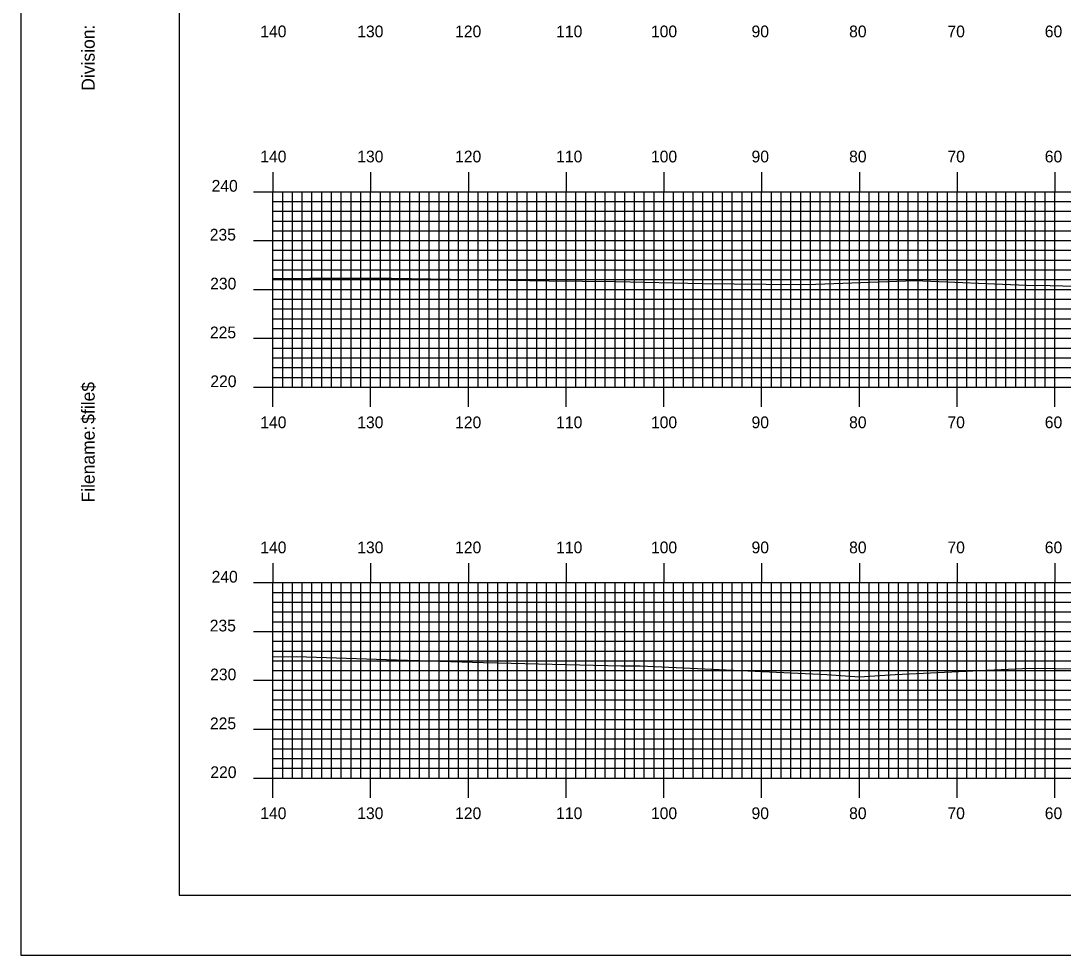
# Model space of a CAD drawing. Extents: x 1803503 to 1803847, y 442591 to 442811.
# Drawn here: x 1803503.4 to 1803610, y 442590.5 to 442686.2 of the extents above; entities that cross this region are included whole.
import ezdxf

# ---------------------------------------------------------------- set-up
doc = ezdxf.new("R2010")
doc.units = 0
for name, color, linetype in [('BORDER', 7, 'Continuous'), ('H_V ANNOTATION', 7, 'Continuous'), ('MAJOR', 7, 'Continuous'), ('MINOR', 7, 'Continuous'), ('PLOT BOUNDARY', 7, 'Continuous'), ('S_Roadway_Centerline', 7, 'Continuous')]:
    doc.layers.add(name, color=color, linetype=linetype)

msp = doc.modelspace()

# ---------------------------------------------------------------- linework, layer by layer
at = {"layer": 'BORDER'}
msp.add_lwpolyline([(1803519.54, 442596.67), (1803839.54, 442596.67), (1803839.54, 442806.67), (1803519.54, 442806.67)], close=True, dxfattribs=at)
at = {"layer": 'MAJOR'}
for p, q in [((1803529.14, 442670.67), (1803529.14, 442668.67)), ((1803539.14, 442670.67), (1803539.14, 442668.67)), ((1803549.14, 442670.67), (1803549.14, 442668.67)), ((1803559.14, 442670.67), (1803559.14, 442668.67)), ((1803569.14, 442670.67), (1803569.14, 442668.67)), ((1803579.14, 442670.67), (1803579.14, 442668.67)), ((1803589.14, 442670.67), (1803589.14, 442668.67)), ((1803599.14, 442670.67), (1803599.14, 442668.67)), ((1803609.14, 442670.67), (1803609.14, 442668.67)), ((1803527.14, 442668.67), (1803529.14, 442668.67)), ((1803529.14, 442668.67), (1803809.14, 442668.67)), ((1803529.14, 442648.67), (1803529.14, 442668.67)), ((1803529.14, 442648.67), (1803529.14, 442668.67)), ((1803529.14, 442668.67), (1803809.14, 442668.67)), ((1803539.14, 442648.67), (1803539.14, 442668.67)), ((1803549.14, 442648.67), (1803549.14, 442668.67)), ((1803559.14, 442648.67), (1803559.14, 442668.67)), ((1803569.14, 442648.67), (1803569.14, 442668.67)), ((1803579.14, 442648.67), (1803579.14, 442668.67)), ((1803589.14, 442648.67), (1803589.14, 442668.67)), ((1803599.14, 442648.67), (1803599.14, 442668.67)), ((1803609.14, 442648.67), (1803609.14, 442668.67)), ((1803527.14, 442663.67), (1803529.14, 442663.67)), ((1803529.14, 442663.67), (1803809.14, 442663.67)), ((1803527.14, 442658.67), (1803529.14, 442658.67)), ((1803529.14, 442658.67), (1803809.14, 442658.67)), ((1803527.14, 442653.67), (1803529.14, 442653.67)), ((1803529.14, 442653.67), (1803809.14, 442653.67)), ((1803527.14, 442648.67), (1803529.14, 442648.67)), ((1803529.14, 442648.67), (1803809.14, 442648.67)), ((1803529.14, 442648.67), (1803809.14, 442648.67)), ((1803529.14, 442646.66), (1803529.14, 442648.67)), ((1803539.14, 442646.66), (1803539.14, 442648.67)), ((1803549.14, 442646.66), (1803549.14, 442648.67)), ((1803559.14, 442646.66), (1803559.14, 442648.67)), ((1803569.14, 442646.66), (1803569.14, 442648.67)), ((1803579.14, 442646.66), (1803579.14, 442648.67)), ((1803589.14, 442646.66), (1803589.14, 442648.67)), ((1803599.14, 442646.66), (1803599.14, 442648.67)), ((1803609.14, 442646.66), (1803609.14, 442648.67)), ((1803529.14, 442630.67), (1803529.14, 442628.67)), ((1803539.14, 442630.67), (1803539.14, 442628.67)), ((1803549.14, 442630.67), (1803549.14, 442628.67)), ((1803559.14, 442630.67), (1803559.14, 442628.67)), ((1803569.14, 442630.67), (1803569.14, 442628.67)), ((1803579.14, 442630.67), (1803579.14, 442628.67)), ((1803589.14, 442630.67), (1803589.14, 442628.67)), ((1803599.14, 442630.67), (1803599.14, 442628.67)), ((1803609.14, 442630.67), (1803609.14, 442628.67)), ((1803527.14, 442628.67), (1803529.14, 442628.67)), ((1803529.14, 442628.67), (1803809.14, 442628.67)), ((1803529.14, 442608.67), (1803529.14, 442628.67)), ((1803529.14, 442608.67), (1803529.14, 442628.67)), ((1803529.14, 442628.67), (1803809.14, 442628.67)), ((1803539.14, 442608.67), (1803539.14, 442628.67)), ((1803549.14, 442608.67), (1803549.14, 442628.67)), ((1803559.14, 442608.67), (1803559.14, 442628.67)), ((1803569.14, 442608.67), (1803569.14, 442628.67)), ((1803579.14, 442608.67), (1803579.14, 442628.67)), ((1803589.14, 442608.67), (1803589.14, 442628.67)), ((1803599.14, 442608.67), (1803599.14, 442628.67)), ((1803609.14, 442608.67), (1803609.14, 442628.67)), ((1803527.14, 442623.67), (1803529.14, 442623.67)), ((1803529.14, 442623.67), (1803809.14, 442623.67)), ((1803527.14, 442618.67), (1803529.14, 442618.67)), ((1803529.14, 442618.67), (1803809.14, 442618.67)), ((1803527.14, 442613.67), (1803529.14, 442613.67)), ((1803529.14, 442613.67), (1803809.14, 442613.67)), ((1803527.14, 442608.67), (1803529.14, 442608.67)), ((1803529.14, 442608.67), (1803809.14, 442608.67)), ((1803529.14, 442608.67), (1803809.14, 442608.67)), ((1803529.14, 442606.66), (1803529.14, 442608.67)), ((1803539.14, 442606.66), (1803539.14, 442608.67)), ((1803549.14, 442606.66), (1803549.14, 442608.67)), ((1803559.14, 442606.66), (1803559.14, 442608.67)), ((1803569.14, 442606.66), (1803569.14, 442608.67)), ((1803579.14, 442606.66), (1803579.14, 442608.67)), ((1803589.14, 442606.66), (1803589.14, 442608.67)), ((1803599.14, 442606.66), (1803599.14, 442608.67)), ((1803609.14, 442606.66), (1803609.14, 442608.67))]:
    msp.add_line(p, q, dxfattribs=at)
at = {"layer": 'MINOR'}
for p, q in [((1803530.14, 442648.67), (1803530.14, 442668.67)), ((1803531.14, 442648.67), (1803531.14, 442668.67)), ((1803532.14, 442648.67), (1803532.14, 442668.67)), ((1803533.14, 442648.67), (1803533.14, 442668.67)), ((1803534.14, 442648.67), (1803534.14, 442668.67)), ((1803535.14, 442648.67), (1803535.14, 442668.67)), ((1803536.14, 442648.67), (1803536.14, 442668.67)), ((1803537.14, 442648.67), (1803537.14, 442668.67)), ((1803538.14, 442648.67), (1803538.14, 442668.67)), ((1803540.14, 442648.67), (1803540.14, 442668.67)), ((1803541.14, 442648.67), (1803541.14, 442668.67)), ((1803542.14, 442648.67), (1803542.14, 442668.67)), ((1803543.14, 442648.67), (1803543.14, 442668.67)), ((1803544.14, 442648.67), (1803544.14, 442668.67)), ((1803545.14, 442648.67), (1803545.14, 442668.67)), ((1803546.14, 442648.67), (1803546.14, 442668.67)), ((1803547.14, 442648.67), (1803547.14, 442668.67)), ((1803548.14, 442648.67), (1803548.14, 442668.67)), ((1803550.14, 442648.67), (1803550.14, 442668.67)), ((1803551.14, 442648.67), (1803551.14, 442668.67)), ((1803552.14, 442648.67), (1803552.14, 442668.67)), ((1803553.14, 442648.67), (1803553.14, 442668.67)), ((1803554.14, 442648.67), (1803554.14, 442668.67)), ((1803555.14, 442648.67), (1803555.14, 442668.67)), ((1803556.14, 442648.67), (1803556.14, 442668.67)), ((1803557.14, 442648.67), (1803557.14, 442668.67)), ((1803558.14, 442648.67), (1803558.14, 442668.67)), ((1803560.14, 442648.67), (1803560.14, 442668.67)), ((1803561.14, 442648.67), (1803561.14, 442668.67)), ((1803562.14, 442648.67), (1803562.14, 442668.67)), ((1803563.14, 442648.67), (1803563.14, 442668.67)), ((1803564.14, 442648.67), (1803564.14, 442668.67)), ((1803565.14, 442648.67), (1803565.14, 442668.67)), ((1803566.14, 442648.67), (1803566.14, 442668.67)), ((1803567.14, 442648.67), (1803567.14, 442668.67)), ((1803568.14, 442648.67), (1803568.14, 442668.67)), ((1803570.14, 442648.67), (1803570.14, 442668.67)), ((1803571.14, 442648.67), (1803571.14, 442668.67)), ((1803572.14, 442648.67), (1803572.14, 442668.67)), ((1803573.14, 442648.67), (1803573.14, 442668.67)), ((1803574.14, 442648.67), (1803574.14, 442668.67)), ((1803575.14, 442648.67), (1803575.14, 442668.67)), ((1803576.14, 442648.67), (1803576.14, 442668.67)), ((1803577.14, 442648.67), (1803577.14, 442668.67)), ((1803578.14, 442648.67), (1803578.14, 442668.67)), ((1803580.14, 442648.67), (1803580.14, 442668.67)), ((1803581.14, 442648.67), (1803581.14, 442668.67)), ((1803582.14, 442648.67), (1803582.14, 442668.67)), ((1803583.14, 442648.67), (1803583.14, 442668.67)), ((1803584.14, 442648.67), (1803584.14, 442668.67)), ((1803585.14, 442648.67), (1803585.14, 442668.67)), ((1803586.14, 442648.67), (1803586.14, 442668.67)), ((1803587.14, 442648.67), (1803587.14, 442668.67)), ((1803588.14, 442648.67), (1803588.14, 442668.67)), ((1803590.14, 442648.67), (1803590.14, 442668.67)), ((1803591.14, 442648.67), (1803591.14, 442668.67)), ((1803592.14, 442648.67), (1803592.14, 442668.67)), ((1803593.14, 442648.67), (1803593.14, 442668.67)), ((1803594.14, 442648.67), (1803594.14, 442668.67)), ((1803595.14, 442648.67), (1803595.14, 442668.67)), ((1803596.14, 442648.67), (1803596.14, 442668.67)), ((1803597.14, 442648.67), (1803597.14, 442668.67)), ((1803598.14, 442648.67), (1803598.14, 442668.67)), ((1803600.14, 442648.67), (1803600.14, 442668.67)), ((1803601.14, 442648.67), (1803601.14, 442668.67)), ((1803602.14, 442648.67), (1803602.14, 442668.67)), ((1803603.14, 442648.67), (1803603.14, 442668.67)), ((1803604.14, 442648.67), (1803604.14, 442668.67)), ((1803605.14, 442648.67), (1803605.14, 442668.67)), ((1803606.14, 442648.67), (1803606.14, 442668.67)), ((1803607.14, 442648.67), (1803607.14, 442668.67)), ((1803608.14, 442648.67), (1803608.14, 442668.67)), ((1803529.14, 442667.67), (1803809.14, 442667.67)), ((1803529.14, 442667.67), (1803531.14, 442667.67)), ((1803529.14, 442666.67), (1803809.14, 442666.67)), ((1803529.14, 442666.67), (1803531.14, 442666.67)), ((1803529.14, 442665.67), (1803809.14, 442665.67)), ((1803529.14, 442665.67), (1803531.14, 442665.67)), ((1803529.14, 442664.67), (1803809.14, 442664.67)), ((1803529.14, 442664.67), (1803531.14, 442664.67)), ((1803529.14, 442662.67), (1803809.14, 442662.67)), ((1803529.14, 442662.67), (1803531.14, 442662.67)), ((1803529.14, 442661.67), (1803809.14, 442661.67)), ((1803529.14, 442661.67), (1803531.14, 442661.67)), ((1803529.14, 442660.67), (1803809.14, 442660.67)), ((1803529.14, 442660.67), (1803531.14, 442660.67)), ((1803529.14, 442659.67), (1803809.14, 442659.67)), ((1803529.14, 442659.67), (1803531.14, 442659.67)), ((1803529.14, 442657.67), (1803809.14, 442657.67)), ((1803529.14, 442657.67), (1803531.14, 442657.67)), ((1803529.14, 442656.67), (1803809.14, 442656.67)), ((1803529.14, 442656.67), (1803531.14, 442656.67)), ((1803529.14, 442655.67), (1803809.14, 442655.67)), ((1803529.14, 442655.67), (1803531.14, 442655.67)), ((1803529.14, 442654.67), (1803809.14, 442654.67)), ((1803529.14, 442654.67), (1803531.14, 442654.67)), ((1803529.14, 442652.67), (1803809.14, 442652.67)), ((1803529.14, 442652.67), (1803531.14, 442652.67)), ((1803529.14, 442651.67), (1803809.14, 442651.67)), ((1803529.14, 442651.67), (1803531.14, 442651.67)), ((1803529.14, 442650.67), (1803809.14, 442650.67)), ((1803529.14, 442650.67), (1803531.14, 442650.67)), ((1803529.14, 442649.67), (1803809.14, 442649.67)), ((1803529.14, 442649.67), (1803531.14, 442649.67)), ((1803530.14, 442608.67), (1803530.14, 442628.67)), ((1803531.14, 442608.67), (1803531.14, 442628.67)), ((1803532.14, 442608.67), (1803532.14, 442628.67)), ((1803533.14, 442608.67), (1803533.14, 442628.67)), ((1803534.14, 442608.67), (1803534.14, 442628.67)), ((1803535.14, 442608.67), (1803535.14, 442628.67)), ((1803536.14, 442608.67), (1803536.14, 442628.67)), ((1803537.14, 442608.67), (1803537.14, 442628.67)), ((1803538.14, 442608.67), (1803538.14, 442628.67)), ((1803540.14, 442608.67), (1803540.14, 442628.67)), ((1803541.14, 442608.67), (1803541.14, 442628.67)), ((1803542.14, 442608.67), (1803542.14, 442628.67)), ((1803543.14, 442608.67), (1803543.14, 442628.67)), ((1803544.14, 442608.67), (1803544.14, 442628.67)), ((1803545.14, 442608.67), (1803545.14, 442628.67)), ((1803546.14, 442608.67), (1803546.14, 442628.67)), ((1803547.14, 442608.67), (1803547.14, 442628.67)), ((1803548.14, 442608.67), (1803548.14, 442628.67)), ((1803550.14, 442608.67), (1803550.14, 442628.67)), ((1803551.14, 442608.67), (1803551.14, 442628.67)), ((1803552.14, 442608.67), (1803552.14, 442628.67)), ((1803553.14, 442608.67), (1803553.14, 442628.67)), ((1803554.14, 442608.67), (1803554.14, 442628.67)), ((1803555.14, 442608.67), (1803555.14, 442628.67)), ((1803556.14, 442608.67), (1803556.14, 442628.67)), ((1803557.14, 442608.67), (1803557.14, 442628.67)), ((1803558.14, 442608.67), (1803558.14, 442628.67)), ((1803560.14, 442608.67), (1803560.14, 442628.67)), ((1803561.14, 442608.67), (1803561.14, 442628.67)), ((1803562.14, 442608.67), (1803562.14, 442628.67)), ((1803563.14, 442608.67), (1803563.14, 442628.67)), ((1803564.14, 442608.67), (1803564.14, 442628.67)), ((1803565.14, 442608.67), (1803565.14, 442628.67)), ((1803566.14, 442608.67), (1803566.14, 442628.67)), ((1803567.14, 442608.67), (1803567.14, 442628.67)), ((1803568.14, 442608.67), (1803568.14, 442628.67)), ((1803570.14, 442608.67), (1803570.14, 442628.67)), ((1803571.14, 442608.67), (1803571.14, 442628.67)), ((1803572.14, 442608.67), (1803572.14, 442628.67)), ((1803573.14, 442608.67), (1803573.14, 442628.67)), ((1803574.14, 442608.67), (1803574.14, 442628.67)), ((1803575.14, 442608.67), (1803575.14, 442628.67)), ((1803576.14, 442608.67), (1803576.14, 442628.67)), ((1803577.14, 442608.67), (1803577.14, 442628.67)), ((1803578.14, 442608.67), (1803578.14, 442628.67)), ((1803580.14, 442608.67), (1803580.14, 442628.67)), ((1803581.14, 442608.67), (1803581.14, 442628.67)), ((1803582.14, 442608.67), (1803582.14, 442628.67)), ((1803583.14, 442608.67), (1803583.14, 442628.67)), ((1803584.14, 442608.67), (1803584.14, 442628.67)), ((1803585.14, 442608.67), (1803585.14, 442628.67)), ((1803586.14, 442608.67), (1803586.14, 442628.67)), ((1803587.14, 442608.67), (1803587.14, 442628.67)), ((1803588.14, 442608.67), (1803588.14, 442628.67)), ((1803590.14, 442608.67), (1803590.14, 442628.67)), ((1803591.14, 442608.67), (1803591.14, 442628.67)), ((1803592.14, 442608.67), (1803592.14, 442628.67)), ((1803593.14, 442608.67), (1803593.14, 442628.67)), ((1803594.14, 442608.67), (1803594.14, 442628.67)), ((1803595.14, 442608.67), (1803595.14, 442628.67)), ((1803596.14, 442608.67), (1803596.14, 442628.67)), ((1803597.14, 442608.67), (1803597.14, 442628.67)), ((1803598.14, 442608.67), (1803598.14, 442628.67)), ((1803600.14, 442608.67), (1803600.14, 442628.67)), ((1803601.14, 442608.67), (1803601.14, 442628.67)), ((1803602.14, 442608.67), (1803602.14, 442628.67)), ((1803603.14, 442608.67), (1803603.14, 442628.67)), ((1803604.14, 442608.67), (1803604.14, 442628.67)), ((1803605.14, 442608.67), (1803605.14, 442628.67)), ((1803606.14, 442608.67), (1803606.14, 442628.67)), ((1803607.14, 442608.67), (1803607.14, 442628.67)), ((1803608.14, 442608.67), (1803608.14, 442628.67)), ((1803529.14, 442627.67), (1803809.14, 442627.67)), ((1803529.14, 442627.67), (1803531.14, 442627.67)), ((1803529.14, 442626.67), (1803809.14, 442626.67)), ((1803529.14, 442626.67), (1803531.14, 442626.67)), ((1803529.14, 442625.67), (1803809.14, 442625.67)), ((1803529.14, 442625.67), (1803531.14, 442625.67)), ((1803529.14, 442624.67), (1803809.14, 442624.67)), ((1803529.14, 442624.67), (1803531.14, 442624.67)), ((1803529.14, 442622.67), (1803809.14, 442622.67)), ((1803529.14, 442622.67), (1803531.14, 442622.67)), ((1803529.14, 442621.67), (1803809.14, 442621.67)), ((1803529.14, 442621.67), (1803531.14, 442621.67)), ((1803529.14, 442620.67), (1803809.14, 442620.67)), ((1803529.14, 442620.67), (1803531.14, 442620.67)), ((1803529.14, 442619.67), (1803809.14, 442619.67)), ((1803529.14, 442619.67), (1803531.14, 442619.67)), ((1803529.14, 442617.67), (1803809.14, 442617.67)), ((1803529.14, 442617.67), (1803531.14, 442617.67)), ((1803529.14, 442616.67), (1803809.14, 442616.67)), ((1803529.14, 442616.67), (1803531.14, 442616.67)), ((1803529.14, 442615.67), (1803809.14, 442615.67)), ((1803529.14, 442615.67), (1803531.14, 442615.67)), ((1803529.14, 442614.67), (1803809.14, 442614.67)), ((1803529.14, 442614.67), (1803531.14, 442614.67)), ((1803529.14, 442612.67), (1803809.14, 442612.67)), ((1803529.14, 442612.67), (1803531.14, 442612.67)), ((1803529.14, 442611.67), (1803809.14, 442611.67)), ((1803529.14, 442611.67), (1803531.14, 442611.67)), ((1803529.14, 442610.67), (1803809.14, 442610.67)), ((1803529.14, 442610.67), (1803531.14, 442610.67)), ((1803529.14, 442609.67), (1803809.14, 442609.67)), ((1803529.14, 442609.67), (1803531.14, 442609.67))]:
    msp.add_line(p, q, dxfattribs=at)
at = {"layer": 'PLOT BOUNDARY'}
msp.add_lwpolyline([(1803503.35, 442590.55), (1803843.35, 442590.55), (1803843.35, 442810.55), (1803503.35, 442810.55)], close=True, dxfattribs=at)
at = {"layer": 'S_Roadway_Centerline'}
for points in [[(1803529.14, 442659.79), (1803532.92, 442659.82), (1803541.28, 442659.81), (1803557.4, 442659.55), (1803564.22, 442659.48), (1803573.05, 442659.26), (1803582.89, 442659.16), (1803584.7, 442659.2), (1803594.81, 442659.57), (1803606.23, 442659.12), (1803608.65, 442659.06), (1803609.95, 442659.03), (1803614.98, 442658.95)], [(1803529.14, 442621.08), (1803531.56, 442621.11), (1803541.79, 442620.75), (1803542.91, 442620.72), (1803550.67, 442620.51), (1803564.77, 442620.16), (1803566.71, 442620.14), (1803585.82, 442619.25), (1803589.17, 442619.04), (1803592.8, 442619.26), (1803606.54, 442619.9), (1803611.86, 442619.84)]]:
    msp.add_lwpolyline(points, dxfattribs=at)

# ---------------------------------------------------------------- texts
at = {"layer": 'BORDER'}
for s, p in [('Division:', (1803510.91, 442679)), ('$file$', (1803510.91, 442644.92)), ('Filename:', (1803510.91, 442636.86))]:
    msp.add_text(s, height=1.339, rotation=90, dxfattribs=at).set_placement(p)
at = {"layer": 'H_V ANNOTATION'}
for s, p in [('140', (1803527.85, 442684.47)), ('130', (1803537.77, 442684.47)), ('120', (1803547.78, 442684.47)), ('110', (1803558.12, 442684.47)), ('100', (1803567.82, 442684.47)), ('90', (1803578.11, 442684.47)), ('80', (1803588.09, 442684.47)), ('70', (1803598.15, 442684.47)), ('60', (1803608.11, 442684.47)), ('140', (1803527.85, 442671.67)), ('130', (1803537.77, 442671.67)), ('120', (1803547.78, 442671.67)), ('110', (1803558.12, 442671.67)), ('100', (1803567.82, 442671.67)), ('90', (1803578.11, 442671.67)), ('80', (1803588.09, 442671.67)), ('70', (1803598.15, 442671.67)), ('60', (1803608.11, 442671.67)), ('240', (1803522.87, 442668.67)), ('235', (1803522.68, 442663.67)), ('230', (1803522.72, 442658.67)), ('225', (1803522.7, 442653.67)), ('220', (1803522.74, 442648.67)), ('140', (1803527.85, 442644.47)), ('130', (1803537.77, 442644.47)), ('120', (1803547.78, 442644.47)), ('110', (1803558.12, 442644.47)), ('100', (1803567.82, 442644.47)), ('90', (1803578.11, 442644.47)), ('80', (1803588.09, 442644.47)), ('70', (1803598.15, 442644.47)), ('60', (1803608.11, 442644.47)), ('140', (1803527.85, 442631.67)), ('130', (1803537.77, 442631.67)), ('120', (1803547.78, 442631.67)), ('110', (1803558.12, 442631.67)), ('100', (1803567.82, 442631.67)), ('90', (1803578.11, 442631.67)), ('80', (1803588.09, 442631.67)), ('70', (1803598.15, 442631.67)), ('60', (1803608.11, 442631.67)), ('240', (1803522.87, 442628.67)), ('235', (1803522.68, 442623.67)), ('230', (1803522.72, 442618.67)), ('225', (1803522.7, 442613.67)), ('220', (1803522.74, 442608.67)), ('140', (1803527.85, 442604.47)), ('130', (1803537.77, 442604.47)), ('120', (1803547.78, 442604.47)), ('110', (1803558.12, 442604.47)), ('100', (1803567.82, 442604.47)), ('90', (1803578.11, 442604.47)), ('80', (1803588.09, 442604.47)), ('70', (1803598.15, 442604.47)), ('60', (1803608.11, 442604.47))]:
    msp.add_text(s, height=1.2, dxfattribs=at).set_placement(p)
at = {"layer": 'MAJOR'}
for p in [(1803529.13, 442648.67), (1803529.13, 442608.67)]:
    msp.add_text('-', height=0.012, dxfattribs=at).set_placement(p)

doc.saveas('drawing.dxf')
